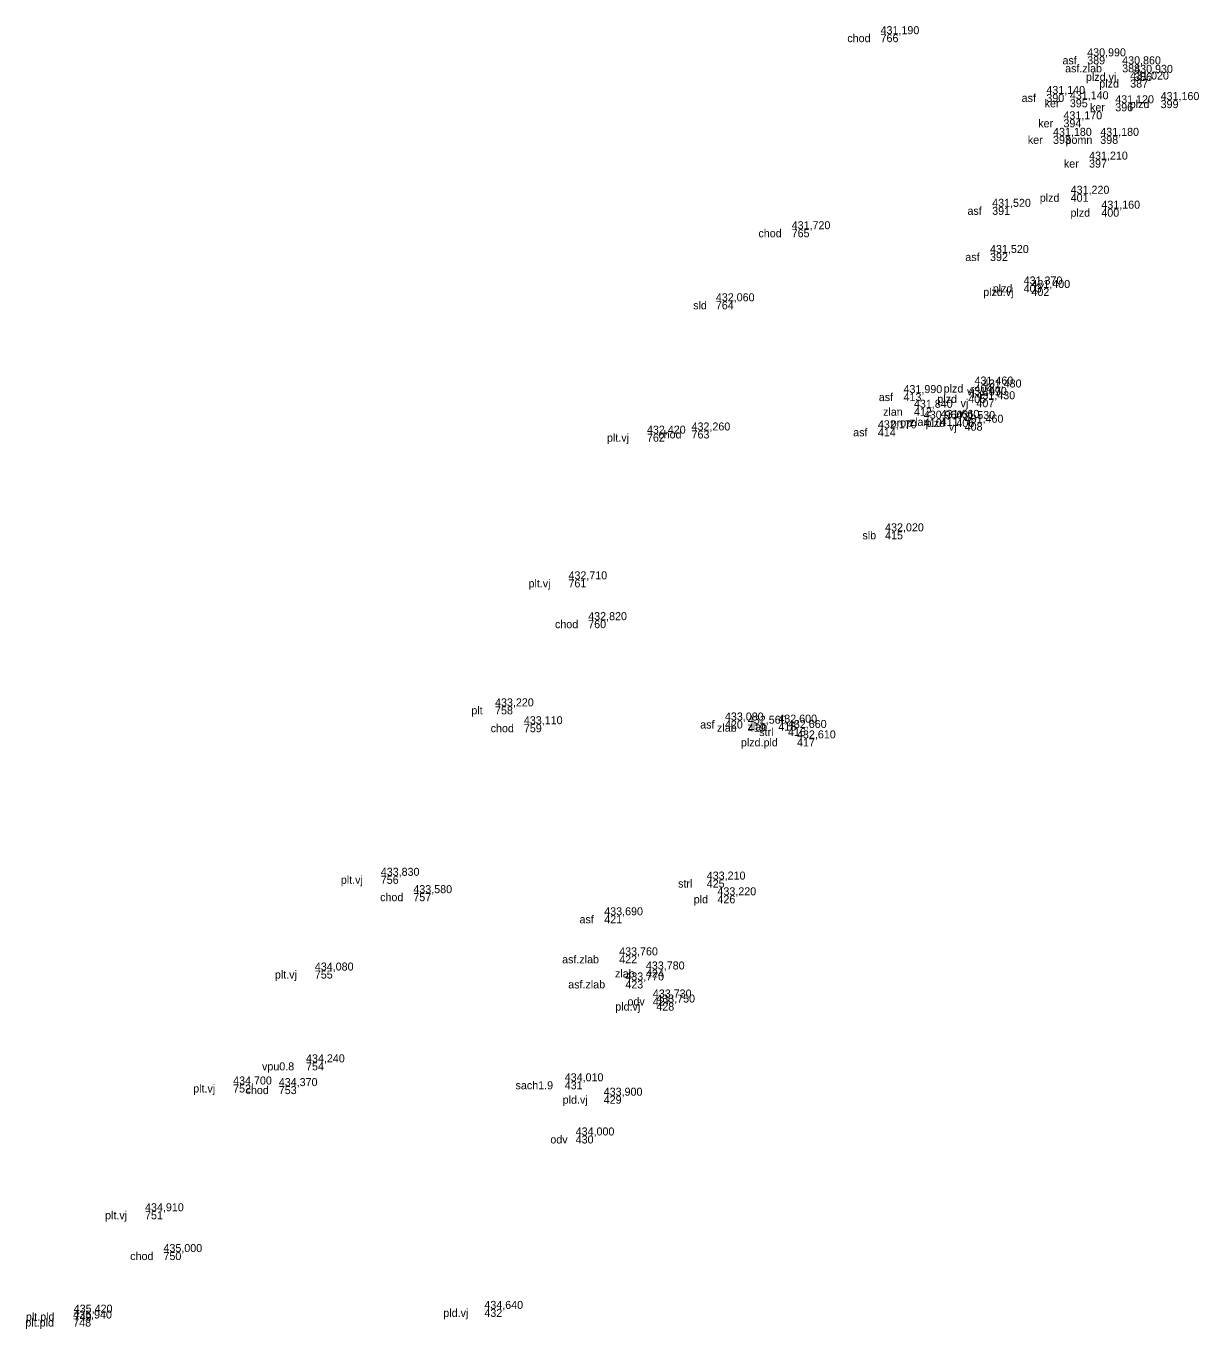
# Model space of a CAD drawing. Extents: x -747136 to -746138, y -1093274 to -1091717.
# Drawn here: x -746660.44 to -746616.51, y -1093031.46 to -1092982.64 of the extents above; entities that cross this region are included whole.
import ezdxf

# ---------------------------------------------------------------- set-up
doc = ezdxf.new("R2010")
doc.units = 0
for name, color, linetype in [('1029', 7, 'Continuous'), ('404', 7, 'Continuous'), ('424', 7, 'Continuous')]:
    doc.layers.add(name, color=color, linetype=linetype)

msp = doc.modelspace()

# ---------------------------------------------------------------- linework, layer by layer
at = {"layer": '404'}
for p, q in [((-746628.43, -1092982.94), (-746628.43, -1092982.94)), ((-746620.69, -1092983.77), (-746620.69, -1092983.77)), ((-746619.38, -1092984.07), (-746619.38, -1092984.07)), ((-746619.08, -1092984.64), (-746619.08, -1092984.64)), ((-746618.93, -1092984.39), (-746618.93, -1092984.39)), ((-746622.22, -1092985.18), (-746622.22, -1092985.18)), ((-746621.34, -1092985.38), (-746621.34, -1092985.38)), ((-746619.64, -1092985.53), (-746619.64, -1092985.53)), ((-746617.94, -1092985.41), (-746617.94, -1092985.41)), ((-746621.58, -1092986.13), (-746621.58, -1092986.13)), ((-746621.97, -1092986.75), (-746621.97, -1092986.75)), ((-746620.2, -1092986.75), (-746620.2, -1092986.75)), ((-746620.62, -1092987.64), (-746620.62, -1092987.64)), ((-746621.31, -1092988.92), (-746621.31, -1092988.92)), ((-746624.25, -1092989.41), (-746624.25, -1092989.41)), ((-746620.16, -1092989.48), (-746620.16, -1092989.48)), ((-746631.76, -1092990.25), (-746631.76, -1092990.25)), ((-746624.33, -1092991.14), (-746624.33, -1092991.14)), ((-746623.07, -1092992.32), (-746623.07, -1092992.32)), ((-746622.78, -1092992.45), (-746622.78, -1092992.45)), ((-746634.6, -1092992.95), (-746634.6, -1092992.95)), ((-746627.57, -1092996.39), (-746627.57, -1092996.39)), ((-746625.15, -1092996.46), (-746625.15, -1092996.46)), ((-746624.91, -1092996.07), (-746624.91, -1092996.07)), ((-746624.6, -1092996.18), (-746624.6, -1092996.18)), ((-746627.18, -1092996.94), (-746627.18, -1092996.94)), ((-746624.84, -1092996.62), (-746624.84, -1092996.62)), ((-746626.81, -1092997.35), (-746626.81, -1092997.35)), ((-746626.18, -1092997.32), (-746626.18, -1092997.32)), ((-746625.59, -1092997.36), (-746625.59, -1092997.36)), ((-746625.28, -1092997.5), (-746625.28, -1092997.5)), ((-746637.18, -1092997.91), (-746637.18, -1092997.91)), ((-746635.51, -1092997.79), (-746635.51, -1092997.79)), ((-746628.53, -1092997.71), (-746628.53, -1092997.71)), ((-746628.26, -1093001.57), (-746628.26, -1093001.57)), ((-746640.12, -1093003.37), (-746640.12, -1093003.37)), ((-746639.38, -1093004.9), (-746639.38, -1093004.9)), ((-746642.87, -1093008.13), (-746642.87, -1093008.13)), ((-746634.26, -1093008.66), (-746634.26, -1093008.66)), ((-746632.26, -1093008.74), (-746632.26, -1093008.74)), ((-746641.79, -1093008.8), (-746641.79, -1093008.8)), ((-746633.4, -1093008.78), (-746633.4, -1093008.78)), ((-746631.9, -1093008.94), (-746631.9, -1093008.94)), ((-746631.56, -1093009.33), (-746631.56, -1093009.33)), ((-746647.15, -1093014.48), (-746647.15, -1093014.48)), ((-746634.94, -1093014.62), (-746634.94, -1093014.62)), ((-746645.93, -1093015.13), (-746645.93, -1093015.13)), ((-746634.54, -1093015.21), (-746634.54, -1093015.21)), ((-746638.78, -1093015.96), (-746638.78, -1093015.96)), ((-746638.22, -1093017.46), (-746638.22, -1093017.46)), ((-746649.62, -1093018.03), (-746649.62, -1093018.03)), ((-746637.22, -1093017.99), (-746637.22, -1093017.99)), ((-746637.99, -1093018.4), (-746637.99, -1093018.4)), ((-746636.96, -1093019.04), (-746636.96, -1093019.04)), ((-746636.83, -1093019.23), (-746636.83, -1093019.23)), ((-746649.95, -1093021.47), (-746649.95, -1093021.47)), ((-746652.68, -1093022.3), (-746652.68, -1093022.3)), ((-746650.97, -1093022.36), (-746650.97, -1093022.36)), ((-746640.26, -1093022.18), (-746640.26, -1093022.18)), ((-746638.8, -1093022.72), (-746638.8, -1093022.72)), ((-746639.85, -1093024.21), (-746639.85, -1093024.21)), ((-746655.98, -1093027.05), (-746655.98, -1093027.05)), ((-746655.29, -1093028.58), (-746655.29, -1093028.58)), ((-746643.27, -1093030.71), (-746643.27, -1093030.71)), ((-746658.67, -1093031.07), (-746658.67, -1093031.07)), ((-746658.65, -1093030.85), (-746658.65, -1093030.85))]:
    msp.add_line(p, q, dxfattribs=at)

# ---------------------------------------------------------------- texts
at = {"layer": '1029'}
for s, p in [('431,190', (-746628.43, -1092982.94)), ('430,990', (-746620.69, -1092983.77)), ('430,860', (-746619.38, -1092984.07)), ('431,020', (-746619.08, -1092984.64)), ('430,930', (-746618.93, -1092984.39)), ('431,140', (-746622.22, -1092985.18)), ('431,140', (-746621.34, -1092985.38)), ('431,120', (-746619.64, -1092985.53)), ('431,160', (-746617.94, -1092985.41)), ('431,170', (-746621.58, -1092986.13)), ('431,180', (-746621.97, -1092986.75)), ('431,180', (-746620.2, -1092986.75)), ('431,210', (-746620.62, -1092987.64)), ('431,220', (-746621.31, -1092988.92)), ('431,520', (-746624.25, -1092989.41)), ('431,160', (-746620.16, -1092989.48)), ('431,720', (-746631.76, -1092990.25)), ('431,520', (-746624.33, -1092991.14)), ('431,370', (-746623.07, -1092992.32)), ('431,400', (-746622.78, -1092992.45)), ('432,060', (-746634.6, -1092992.95)), ('431,460', (-746624.91, -1092996.07)), ('431,480', (-746624.6, -1092996.18)), ('431,990', (-746627.57, -1092996.39)), ('431,470', (-746625.15, -1092996.46)), ('431,430', (-746624.84, -1092996.62)), ('431,840', (-746627.18, -1092996.94)), ('431,660', (-746626.18, -1092997.32)), ('432,260', (-746635.51, -1092997.79)), ('432,170', (-746628.53, -1092997.71)), ('430,960', (-746626.81, -1092997.35)), ('431,530', (-746625.59, -1092997.36)), ('431,460', (-746625.28, -1092997.5)), ('432,420', (-746637.18, -1092997.91)), ('432,020', (-746628.26, -1093001.57)), ('432,710', (-746640.12, -1093003.37)), ('432,820', (-746639.38, -1093004.9)), ('433,220', (-746642.87, -1093008.13)), ('433,110', (-746641.79, -1093008.8)), ('433,080', (-746634.26, -1093008.66)), ('432,560', (-746633.4, -1093008.78)), ('432,600', (-746632.26, -1093008.74)), ('432,660', (-746631.9, -1093008.94)), ('432,610', (-746631.56, -1093009.33)), ('433,830', (-746647.15, -1093014.48)), ('433,210', (-746634.94, -1093014.62)), ('433,580', (-746645.93, -1093015.13)), ('433,220', (-746634.54, -1093015.21)), ('433,690', (-746638.78, -1093015.96)), ('433,760', (-746638.22, -1093017.46)), ('434,080', (-746649.62, -1093018.03)), ('433,780', (-746637.22, -1093017.99)), ('433,770', (-746637.99, -1093018.4)), ('433,730', (-746636.96, -1093019.04)), ('433,750', (-746636.83, -1093019.23)), ('434,240', (-746649.95, -1093021.47)), ('434,010', (-746640.26, -1093022.18)), ('434,700', (-746652.68, -1093022.3)), ('434,370', (-746650.97, -1093022.36)), ('433,900', (-746638.8, -1093022.72)), ('434,000', (-746639.85, -1093024.21)), ('434,910', (-746655.98, -1093027.05)), ('435,000', (-746655.29, -1093028.58)), ('435,420', (-746658.65, -1093030.85)), ('434,640', (-746643.27, -1093030.71)), ('435,940', (-746658.67, -1093031.07))]:
    msp.add_text(s, height=0.3, dxfattribs=at).set_placement(p)
at = {"layer": '424'}
for s, p in [(' chod', (-746629.786, -1092983.24)), ('766', (-746628.43, -1092983.24)), (' asf', (-746621.727, -1092984.07)), ('389', (-746620.69, -1092984.07)), (' asf.zlab', (-746621.631, -1092984.37)), ('388', (-746619.38, -1092984.37)), (' plzd.vj', (-746620.848, -1092984.69)), (' plzd', (-746620.348, -1092984.94)), ('387', (-746619.08, -1092984.94)), ('386', (-746618.93, -1092984.69)), (' asf', (-746623.257, -1092985.48)), ('390', (-746622.22, -1092985.48)), (' ker', (-746622.396, -1092985.68)), ('395', (-746621.34, -1092985.68)), (' ker', (-746620.696, -1092985.83)), ('396', (-746619.64, -1092985.83)), (' plzd', (-746619.208, -1092985.71)), ('399', (-746617.94, -1092985.71)), (' ker', (-746622.636, -1092986.43)), ('394', (-746621.58, -1092986.43)), (' ker', (-746623.026, -1092987.05)), ('393', (-746621.97, -1092987.05)), ('398', (-746620.2, -1092987.05)), (' pomn', (-746621.612, -1092987.05)), (' ker', (-746621.676, -1092987.94)), ('397', (-746620.62, -1092987.94)), (' plzd', (-746622.578, -1092989.22)), ('401', (-746621.31, -1092989.22)), (' asf', (-746625.287, -1092989.71)), ('391', (-746624.25, -1092989.71)), (' plzd', (-746621.428, -1092989.78)), ('400', (-746620.16, -1092989.78)), (' chod', (-746633.116, -1092990.55)), ('765', (-746631.76, -1092990.55)), (' asf', (-746625.367, -1092991.44)), ('392', (-746624.33, -1092991.44)), (' plzd.vj', (-746624.698, -1092992.75)), (' plzd', (-746624.338, -1092992.62)), ('403', (-746623.07, -1092992.62)), ('402', (-746622.78, -1092992.75)), (' sld', (-746635.561, -1092993.25)), ('764', (-746634.6, -1092993.25)), (' plzd', (-746626.178, -1092996.37)), (' asf', (-746628.607, -1092996.69)), ('413', (-746627.57, -1092996.69)), (' plzd', (-746626.418, -1092996.76)), (' vj', (-746625.304, -1092996.48)), ('405', (-746625.15, -1092996.76)), ('404', (-746624.91, -1092996.37)), ('409', (-746624.6, -1092996.48)), (' zlan', (-746628.448, -1092997.24)), ('412', (-746627.18, -1092997.24)), (' vj', (-746625.544, -1092996.92)), ('407', (-746624.84, -1092996.92)), (' prop', (-746628.161, -1092997.65)), (' zlan', (-746627.448, -1092997.62)), ('410', (-746626.81, -1092997.65)), (' plzd', (-746626.858, -1092997.66)), ('411', (-746626.18, -1092997.62)), (' vj', (-746625.984, -1092997.8)), ('406', (-746625.59, -1092997.66)), ('408', (-746625.28, -1092997.8)), (' plt.vj', (-746638.788, -1092998.21)), ('762', (-746637.18, -1092998.21)), (' chod', (-746636.866, -1092998.09)), ('763', (-746635.51, -1092998.09)), (' asf', (-746629.567, -1092998.01)), ('414', (-746628.53, -1092998.01)), (' slb', (-746629.221, -1093001.87)), ('415', (-746628.26, -1093001.87)), (' plt.vj', (-746641.728, -1093003.67)), ('761', (-746640.12, -1093003.67)), (' chod', (-746640.736, -1093005.2)), ('760', (-746639.38, -1093005.2)), (' plt', (-746643.869, -1093008.43)), ('758', (-746642.87, -1093008.43)), (' asf', (-746635.297, -1093008.96)), ('420', (-746634.26, -1093008.96)), (' zlab', (-746633.528, -1093009.04)), ('418', (-746632.26, -1093009.04)), (' chod', (-746643.146, -1093009.1)), ('759', (-746641.79, -1093009.1)), (' zlab', (-746634.668, -1093009.08)), ('419', (-746633.4, -1093009.08)), (' strl', (-746633.086, -1093009.24)), ('416', (-746631.9, -1093009.24)), (' plzd.pld', (-746633.773, -1093009.63)), ('417', (-746631.56, -1093009.63)), (' plt.vj', (-746648.758, -1093014.78)), ('756', (-746647.15, -1093014.78)), (' strl', (-746636.126, -1093014.92)), ('425', (-746634.94, -1093014.92)), (' chod', (-746647.286, -1093015.43)), ('757', (-746645.93, -1093015.43)), (' pld', (-746635.539, -1093015.51)), ('426', (-746634.54, -1093015.51)), (' asf', (-746639.817, -1093016.26)), ('421', (-746638.78, -1093016.26)), (' asf.zlab', (-746640.471, -1093017.76)), ('422', (-746638.22, -1093017.76)), (' plt.vj', (-746651.228, -1093018.33)), ('755', (-746649.62, -1093018.33)), (' zlab', (-746638.488, -1093018.29)), ('424', (-746637.22, -1093018.29)), (' asf.zlab', (-746640.241, -1093018.7)), ('423', (-746637.99, -1093018.7)), (' pld.vj', (-746638.479, -1093019.53)), (' odv', (-746638.02, -1093019.34)), ('427', (-746636.96, -1093019.34)), ('428', (-746636.83, -1093019.53)), (' vpu0.8', (-746651.71, -1093021.77)), ('754', (-746649.95, -1093021.77)), (' plt.vj', (-746654.288, -1093022.6)), ('752', (-746652.68, -1093022.6)), (' chod', (-746652.326, -1093022.66)), ('753', (-746650.97, -1093022.66)), (' sach1.9', (-746642.213, -1093022.48)), ('431', (-746640.26, -1093022.48)), (' pld.vj', (-746640.449, -1093023.02)), ('429', (-746638.8, -1093023.02)), (' odv', (-746640.91, -1093024.51)), ('430', (-746639.85, -1093024.51)), (' plt.vj', (-746657.588, -1093027.35)), ('751', (-746655.98, -1093027.35)), (' chod', (-746656.646, -1093028.88)), ('750', (-746655.29, -1093028.88)), (' pld.vj', (-746644.919, -1093031.01)), ('432', (-746643.27, -1093031.01)), (' plt.pld', (-746660.574, -1093031.37)), (' plt.pld', (-746660.554, -1093031.15)), ('748', (-746658.67, -1093031.37)), ('749', (-746658.65, -1093031.15))]:
    msp.add_text(s, height=0.3, dxfattribs=at).set_placement(p)

doc.saveas('drawing.dxf')
